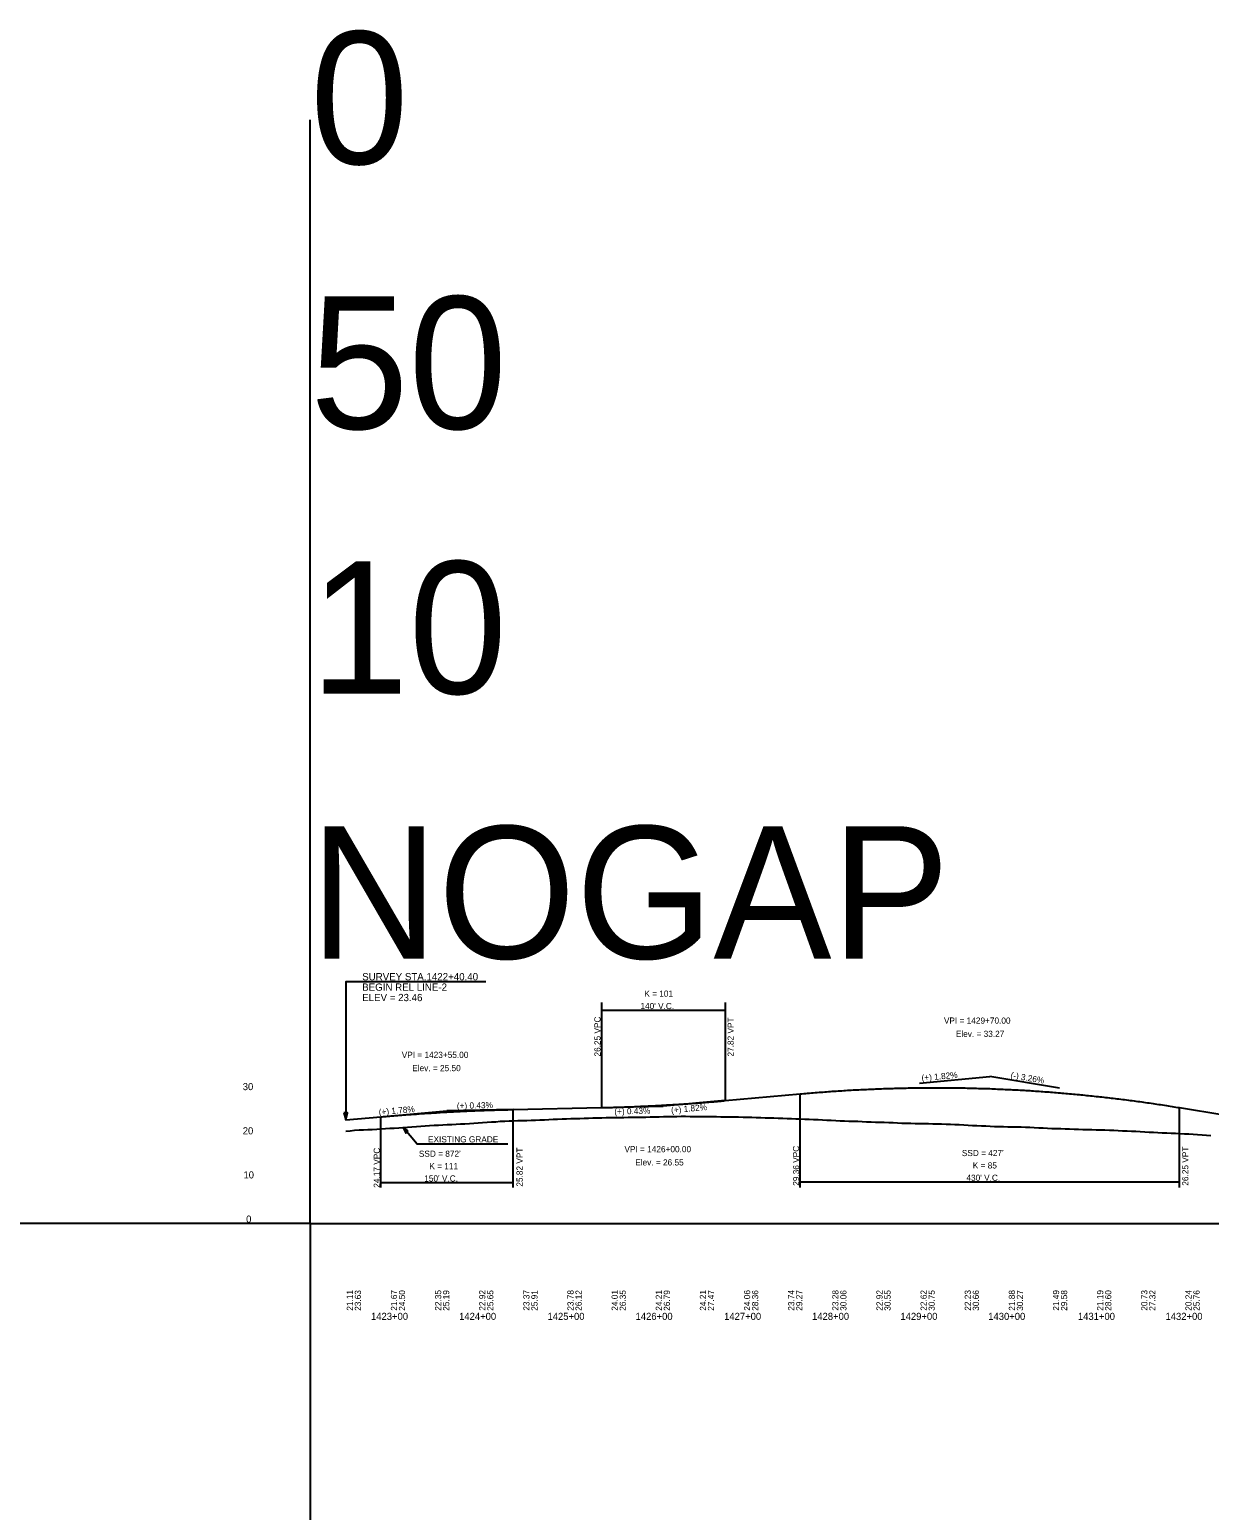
# Model space of a CAD drawing. Extents: x 2360994 to 2383826, y 330623 to 403123.
# Drawn here: x 2368508 to 2369844, y 381548 to 383225 of the extents above; entities that cross this region are included whole.
import ezdxf

# ---------------------------------------------------------------- set-up
doc = ezdxf.new("R2010")
doc.units = 0
for name, color, linetype in [('RD_DDB_ElevTX', 7, 'Continuous'), ('RD_DDB_GradeTX', 7, 'Continuous'), ('RD_DDB_Profile_EX', 7, 'Continuous'), ('RD_DDB_Profile_Lbl', 7, 'Continuous'), ('RD_DDB_Profile_PR', 7, 'Continuous'), ('RD_DDB_StaTX', 7, 'Continuous'), ('RD_DDB_StripGrade', 7, 'Continuous'), ('RD_DDB_VCLbl', 7, 'Continuous'), ('RD_GPK_Profile_Cell', 7, 'Continuous'), ('RD_SHT_Misc1', 7, 'Continuous'), ('RD_TX_Profile', 7, 'Continuous')]:
    doc.layers.add(name, color=color, linetype=linetype)

msp = doc.modelspace()

# ---------------------------------------------------------------- linework, layer by layer
at = {"layer": 'RD_DDB_GradeTX'}
for p, q in [((2369515.9, 382032), (2369595.6, 382039.2)), ((2369674.5, 382026.3), (2369595.6, 382039.2)), ((2369295.6, 382012), (2369225.6, 382005.6)), ((2368905.6, 381993.7), (2368980.6, 382000.4)), ((2369055.6, 382002), (2368980.6, 382000.4)), ((2369155.6, 382004.1), (2369225.6, 382005.6))]:
    msp.add_line(p, q, dxfattribs=at)
at = {"layer": 'RD_DDB_Profile_EX'}
for points in [[(2368866, 381977.5), (2368871, 381978), (2368876, 381978.5), (2368881, 381978.9), (2368886, 381979.1), (2368891, 381979.3), (2368896, 381979.5), (2368901, 381979.7), (2368906, 381980.1), (2368911, 381980.4), (2368916, 381980.7), (2368921, 381981), (2368926, 381981.3), (2368931, 381981.7), (2368936, 381982.1), (2368941, 381982.5), (2368946, 381982.9), (2368951, 381983.2), (2368956, 381983.5), (2368961, 381983.8), (2368966, 381984.1), (2368971, 381984.4), (2368976, 381984.7), (2368981, 381984.9), (2368986, 381985.1), (2368991, 381985.3), (2368996, 381985.6), (2369001, 381985.9), (2369006, 381986.2), (2369011, 381986.6), (2369016, 381986.9), (2369021, 381987.2), (2369026, 381987.5), (2369031, 381987.9), (2369036, 381988.2), (2369041, 381988.6), (2369046, 381988.8), (2369051, 381989.1), (2369056, 381989.3), (2369061, 381989.5), (2369066, 381989.6), (2369071, 381989.6), (2369076, 381989.8), (2369081, 381990), (2369086, 381990.2), (2369091, 381990.4), (2369096, 381990.6), (2369101, 381990.9), (2369106, 381991.1), (2369111, 381991.3), (2369116, 381991.5), (2369121, 381991.7), (2369126, 381991.8), (2369131, 381991.9), (2369136, 381992), (2369141, 381992.2), (2369146, 381992.5), (2369151, 381992.7), (2369156, 381992.7), (2369161, 381992.8), (2369166, 381992.8), (2369171, 381992.9), (2369176, 381992.9), (2369181, 381993.1), (2369186, 381993.2), (2369191, 381993.3), (2369196, 381993.4), (2369201, 381993.4), (2369206, 381993.4), (2369211, 381993.5), (2369216, 381993.6), (2369221, 381993.7), (2369226, 381993.9), (2369231, 381994.1), (2369236, 381994.2), (2369241, 381994.2), (2369246, 381994.3), (2369251, 381994.3), (2369256, 381994.2), (2369261, 381994.2), (2369266, 381994.1), (2369271, 381994), (2369276, 381993.9), (2369281, 381993.9), (2369286, 381993.9), (2369291, 381993.8), (2369296, 381993.7), (2369301, 381993.7), (2369306, 381993.6), (2369311, 381993.5), (2369316, 381993.4), (2369321, 381993.3), (2369326, 381993.2), (2369331, 381993.1), (2369336, 381992.9), (2369341, 381992.7), (2369346, 381992.6), (2369351, 381992.4), (2369356, 381992.2), (2369361, 381992), (2369366, 381991.9)], [(2369366, 381991.9), (2369371, 381991.7), (2369376, 381991.6), (2369381, 381991.4), (2369386, 381991.2), (2369391, 381991), (2369396, 381990.7), (2369401, 381990.5), (2369406, 381990.2), (2369411, 381990), (2369416, 381989.8), (2369421, 381989.5), (2369426, 381989.3), (2369431, 381989.1), (2369436, 381988.9), (2369441, 381988.8), (2369446, 381988.6), (2369451, 381988.4), (2369456, 381988.1), (2369461, 381988), (2369466, 381987.8), (2369471, 381987.6), (2369476, 381987.5), (2369481, 381987.3), (2369486, 381987.1), (2369491, 381986.9), (2369496, 381986.7), (2369501, 381986.6), (2369506, 381986.4), (2369511, 381986.2), (2369516, 381986.2), (2369521, 381986.1), (2369526, 381986), (2369531, 381985.9), (2369536, 381985.7), (2369541, 381985.7), (2369546, 381985.5), (2369551, 381985.3), (2369556, 381985.1), (2369561, 381984.9), (2369566, 381984.6), (2369571, 381984.1), (2369576, 381984), (2369581, 381983.8), (2369586, 381983.6), (2369591, 381983.4), (2369596, 381983.1), (2369601, 381982.9), (2369606, 381982.7), (2369611, 381982.6), (2369616, 381982.5), (2369621, 381982.4), (2369626, 381982.3), (2369631, 381982.2), (2369636, 381982), (2369641, 381981.8), (2369646, 381981.5), (2369651, 381981.3), (2369656, 381981.1), (2369661, 381980.9), (2369666, 381980.6), (2369671, 381980.5), (2369676, 381980.3), (2369681, 381980.1), (2369686, 381980), (2369691, 381979.8), (2369696, 381979.6), (2369701, 381979.5), (2369706, 381979.3), (2369711, 381979.2), (2369716, 381979.1), (2369721, 381979), (2369726, 381978.8), (2369731, 381978.7), (2369736, 381978.5), (2369741, 381978.3), (2369746, 381978), (2369751, 381977.8), (2369756, 381977.5), (2369761, 381977.3), (2369766, 381977.1), (2369771, 381976.8), (2369776, 381976.5), (2369781, 381976.2), (2369786, 381975.9), (2369791, 381975.6), (2369796, 381975.4), (2369801, 381975.2), (2369806, 381975), (2369811, 381974.8), (2369816, 381974.5), (2369821, 381974.3), (2369826, 381974), (2369831, 381973.7), (2369836, 381973.4), (2369841, 381973), (2369846, 381972.6)]]:
    msp.add_lwpolyline(points, dxfattribs=at)
at = {"layer": 'RD_DDB_Profile_PR'}
for p, q in [((2369295.6, 382012), (2369380.6, 382019.7)), ((2369055.6, 382002), (2369155.6, 382004.1)), ((2369810.6, 382004.1), (2369860.6, 381996)), ((2368866, 381990.2), (2368905.6, 381993.7))]:
    msp.add_line(p, q, dxfattribs=at)
for points in [[(2369155.6, 382004.1), (2369158.4, 382004.2), (2369161.2, 382004.2), (2369164, 382004.3), (2369166.8, 382004.4), (2369169.6, 382004.5), (2369172.4, 382004.6), (2369175.2, 382004.6), (2369178, 382004.7), (2369180.8, 382004.8), (2369183.6, 382004.9), (2369186.4, 382005), (2369189.2, 382005.1), (2369192, 382005.2), (2369194.8, 382005.3), (2369197.6, 382005.5), (2369200.4, 382005.6), (2369203.2, 382005.7), (2369206, 382005.8), (2369208.8, 382006), (2369211.6, 382006.1), (2369214.4, 382006.2), (2369217.2, 382006.4), (2369220, 382006.5), (2369222.8, 382006.7), (2369225.6, 382006.8), (2369228.4, 382007), (2369231.2, 382007.2), (2369234, 382007.3), (2369236.8, 382007.5), (2369239.6, 382007.7), (2369242.4, 382007.8), (2369245.2, 382008), (2369248, 382008.2), (2369250.8, 382008.4), (2369253.6, 382008.6), (2369256.4, 382008.8), (2369259.2, 382009), (2369262, 382009.2), (2369264.8, 382009.4), (2369267.6, 382009.6), (2369270.4, 382009.8), (2369273.2, 382010.1), (2369276, 382010.3), (2369278.8, 382010.5), (2369281.6, 382010.7), (2369284.4, 382011), (2369287.2, 382011.2), (2369290, 382011.5), (2369292.8, 382011.7), (2369295.6, 382012)], [(2369380.6, 382019.7), (2369389.2, 382020.4), (2369397.8, 382021.2), (2369406.4, 382021.8), (2369415, 382022.5), (2369423.6, 382023), (2369432.2, 382023.6), (2369440.8, 382024.1), (2369449.4, 382024.5), (2369458, 382024.9), (2369466.6, 382025.3), (2369475.2, 382025.6), (2369483.8, 382025.9), (2369492.4, 382026.1), (2369501, 382026.3), (2369509.6, 382026.5), (2369518.2, 382026.6), (2369526.8, 382026.6), (2369535.4, 382026.7), (2369544, 382026.6), (2369552.6, 382026.6), (2369561.2, 382026.5), (2369569.8, 382026.3), (2369578.4, 382026.1), (2369587, 382025.8), (2369595.6, 382025.6), (2369604.2, 382025.2), (2369612.8, 382024.8), (2369621.4, 382024.4), (2369630, 382024), (2369638.6, 382023.5), (2369647.2, 382022.9), (2369655.8, 382022.3), (2369664.4, 382021.7), (2369673, 382021), (2369681.6, 382020.3), (2369690.2, 382019.5), (2369698.8, 382018.7), (2369707.4, 382017.8), (2369716, 382016.9), (2369724.6, 382016), (2369733.2, 382015), (2369741.8, 382014), (2369750.4, 382012.9), (2369759, 382011.8), (2369767.6, 382010.6), (2369776.2, 382009.4), (2369784.8, 382008.1), (2369793.4, 382006.9), (2369802, 382005.5), (2369810.6, 382004.1)], [(2368905.6, 381993.7), (2368908.6, 381994), (2368911.6, 381994.2), (2368914.6, 381994.5), (2368917.6, 381994.7), (2368920.6, 381995), (2368923.6, 381995.2), (2368926.6, 381995.5), (2368929.6, 381995.7), (2368932.6, 381995.9), (2368935.6, 381996.2), (2368938.6, 381996.4), (2368941.6, 381996.6), (2368944.6, 381996.8), (2368947.6, 381997), (2368950.6, 381997.3), (2368953.6, 381997.5), (2368956.6, 381997.7), (2368959.6, 381997.9), (2368962.6, 381998), (2368965.6, 381998.2), (2368968.6, 381998.4), (2368971.6, 381998.6), (2368974.6, 381998.8), (2368977.6, 381998.9), (2368980.6, 381999.1), (2368983.6, 381999.3), (2368986.6, 381999.4), (2368989.6, 381999.6), (2368992.6, 381999.7), (2368995.6, 381999.9), (2368998.6, 382000), (2369001.6, 382000.2), (2369004.6, 382000.3), (2369007.6, 382000.4), (2369010.6, 382000.6), (2369013.6, 382000.7), (2369016.6, 382000.8), (2369019.6, 382000.9), (2369022.6, 382001), (2369025.6, 382001.1), (2369028.6, 382001.2), (2369031.6, 382001.3), (2369034.6, 382001.4), (2369037.6, 382001.5), (2369040.6, 382001.6), (2369043.6, 382001.7), (2369046.6, 382001.8), (2369049.6, 382001.8), (2369052.6, 382001.9), (2369055.6, 382002)]]:
    msp.add_spline(points, degree=3, dxfattribs=at)
at = {"layer": 'RD_DDB_VCLbl'}
for p, q in [((2369155.6, 382123.2), (2369155.6, 382004.1)), ((2369155.6, 382114.5), (2369295.6, 382114.5)), ((2369295.6, 382123.2), (2369295.6, 382012)), ((2369380.6, 381913.5), (2369380.6, 382019.7)), ((2369055.6, 381913.5), (2369055.6, 382002)), ((2369810.6, 381913.5), (2369810.6, 382004.1)), ((2368905.6, 381913.5), (2368905.6, 381993.7)), ((2368905.6, 381919.2), (2369055.6, 381919.2)), ((2369380.6, 381919.9), (2369810.6, 381919.9))]:
    msp.add_line(p, q, dxfattribs=at)
at = {"layer": 'RD_GPK_Profile_Cell'}
for q in [(2368825.6, 383122.9), (2370625.6, 381872.9), (2368825.6, 380622.9)]:
    msp.add_line((2368825.6, 381872.9), q, dxfattribs=at)
at = {"layer": 'RD_SHT_Misc1'}
msp.add_line((2368825.6, 381872.9), (2363729.6, 381872.9), dxfattribs=at)
at = {"layer": 'RD_TX_Profile'}
for p, q in [((2369024.6, 382146.5), (2368879.6, 382146.5)), ((2369049.4, 381962.7), (2368954.2, 381962.7))]:
    msp.add_line(p, q, dxfattribs=at)
for points in [[(2368879.6, 382146.5), (2368866, 382146.5), (2368866, 381990.2)], [(2368954.2, 381962.7), (2368947, 381962.7), (2368931, 381981.7)]]:
    msp.add_lwpolyline(points, dxfattribs=at)
for points in [[(2368863.8, 381998.1), (2368866, 381990.2), (2368868.1, 381998.1)], [(2368936.7, 381977.7), (2368931, 381981.7), (2368933.9, 381975.3)]]:
    msp.add_lwpolyline(points, close=True, dxfattribs=at)

# ---------------------------------------------------------------- texts
at = {"layer": 'RD_DDB_ElevTX'}
for s, p in [('30', (2368749.3, 382023.9)), ('20', (2368749.3, 381973.9)), ('10', (2368750.1, 381923.9)), ('0', (2368753.1, 381873.9))]:
    msp.add_text(s, height=8, dxfattribs=at).set_placement(p)
at = {"layer": 'RD_DDB_GradeTX'}
for s, rotation, p in [('(+) 1.82%', 5.1872, (2369518.6, 382034.2)), ('(-) 3.26%', 350.7348, (2369618.6, 382037.5)), ('(+) 1.78%', 5.088, (2368903.7, 381995.5)), ('(+) 0.43%', 1.2234, (2368991.9, 382002.7)), ('(+) 0.43%', 1.2234, (2369170.3, 381996.3)), ('(+) 1.82%', 5.1872, (2369234.8, 381997.7))]:
    msp.add_text(s, height=7, rotation=rotation, dxfattribs=at).set_placement(p)
at = {"layer": 'RD_DDB_Profile_Lbl'}
for s, p in [('VPI = 1429+70.00', (2369543.6, 382099.2)), ('Elev. = 33.27', (2369557.1, 382084.2)), ('VPI = 1423+55.00', (2368929.4, 382060.4)), ('Elev. = 25.50', (2368941.3, 382045.4)), ('VPI = 1426+00.00', (2369181.7, 381953.6)), ('Elev. = 26.55', (2369193.9, 381938.6))]:
    msp.add_text(s, height=7, dxfattribs=at).set_placement(p)
at = {"layer": 'RD_DDB_StaTX'}
for s, p in [('1423+00', (2368894.6, 381763.7)), ('1424+00', (2368994.4, 381763.7)), ('1425+00', (2369094.5, 381763.7)), ('1426+00', (2369194.3, 381763.7)), ('1427+00', (2369294.6, 381763.7)), ('1428+00', (2369394.2, 381763.7)), ('1429+00', (2369494.3, 381763.7)), ('1430+00', (2369593.8, 381763.7)), ('1431+00', (2369695.4, 381763.7)), ('1432+00', (2369794.6, 381763.7))]:
    msp.add_text(s, height=8, dxfattribs=at).set_placement(p)
at = {"layer": 'RD_DDB_StripGrade'}
for s, p in [('26.25 VPC', (2369154.6, 382062)), ('27.82 VPT', (2369305.5, 382062)), ('24.17 VPC', (2368904.6, 381913.4)), ('25.82 VPT', (2369066.4, 381914.6)), ('29.36 VPC', (2369379.6, 381915.6)), ('26.25 VPT', (2369820.5, 381915.7)), ('21.11', (2368874.1, 381774.1)), ('23.63', (2368883.2, 381774)), ('21.67', (2368924.1, 381774.1)), ('24.50', (2368933.2, 381774)), ('22.35', (2368974.1, 381774.1)), ('25.19', (2368983.2, 381774)), ('22.92', (2369024.1, 381774.1)), ('25.65', (2369033.2, 381774)), ('23.37', (2369074.1, 381774.1)), ('25.91', (2369083.2, 381774)), ('23.78', (2369124.1, 381774.1)), ('26.12', (2369133.2, 381774)), ('24.01', (2369174.1, 381774.1)), ('26.35', (2369183.2, 381774)), ('24.21', (2369224.1, 381774.1)), ('26.79', (2369233.2, 381774)), ('24.21', (2369274.1, 381774.1)), ('27.47', (2369283.2, 381774)), ('24.06', (2369324.1, 381774.1)), ('28.36', (2369333.2, 381774)), ('23.74', (2369374.1, 381774.1)), ('29.27', (2369383.2, 381774)), ('23.28', (2369424.1, 381774.1)), ('30.06', (2369433.2, 381774)), ('22.92', (2369474.1, 381774.1)), ('30.55', (2369483.2, 381774)), ('22.62', (2369524.1, 381774.1)), ('30.75', (2369533.2, 381774)), ('22.23', (2369574.1, 381774.1)), ('30.66', (2369583.2, 381774)), ('21.88', (2369624.1, 381774.1)), ('30.27', (2369633.2, 381774)), ('21.49', (2369674.1, 381774.1)), ('29.58', (2369683.2, 381774)), ('21.19', (2369724.1, 381774.1)), ('28.60', (2369733.2, 381774)), ('20.73', (2369774.1, 381774.1)), ('27.32', (2369783.2, 381774)), ('20.24', (2369824.1, 381774.1)), ('25.76', (2369833.2, 381774))]:
    msp.add_text(s, height=7, rotation=90, dxfattribs=at).set_placement(p)
at = {"layer": 'RD_DDB_VCLbl'}
for s, p in [('K = 101', (2369204.2, 382129.7)), ("140' V.C.", (2369199.8, 382115.7)), ("SSD = 872'", (2368948.8, 381948.4)), ("SSD = 427'", (2369563.9, 381949.2)), ('K = 111', (2368960.7, 381934.4)), ("430' V.C.", (2369569.1, 381921.2)), ('K = 85', (2369576.3, 381935.2)), ("150' V.C.", (2368954.9, 381920.4))]:
    msp.add_text(s, height=7, dxfattribs=at).set_placement(p)
at = {"layer": 'RD_GPK_Profile_Cell'}
for s, p in [('0', (2368825.6, 383072.9)), ('50', (2368825.6, 382772.9)), ('10', (2368825.6, 382472.9)), ('NOGAP', (2368825.6, 382172.9))]:
    msp.add_text(s, height=150, dxfattribs=at).set_placement(p)
at = {"layer": 'RD_TX_Profile'}
for s, height, p in [('SURVEY STA.1422+40.40', 8.235, (2368884.6, 382148.3)), ('BEGIN REL LINE-2', 8.235, (2368884.6, 382136.5)), ('ELEV = 23.46', 8.235, (2368884.6, 382124.7)), ('EXISTING GRADE', 7, (2368959.2, 381964.7))]:
    msp.add_text(s, height=height, dxfattribs=at).set_placement(p)

doc.saveas('drawing.dxf')
